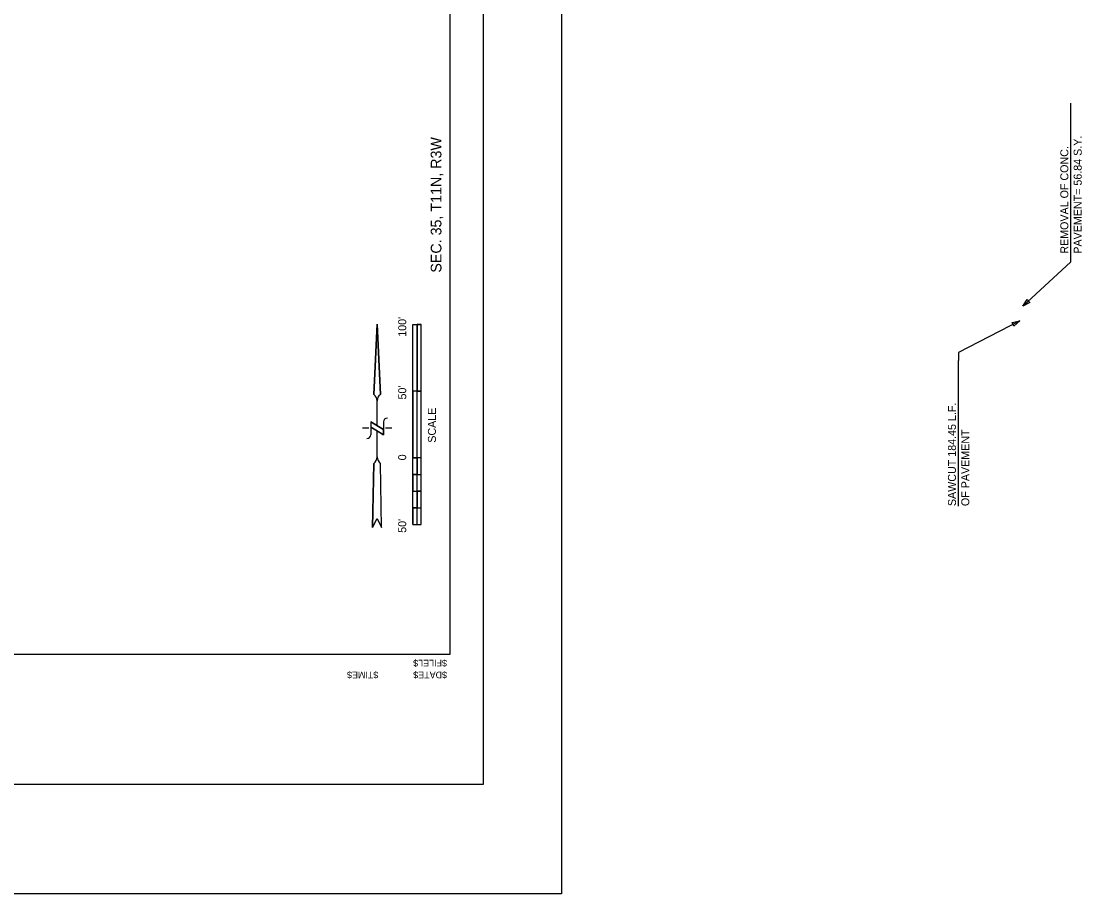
# Model space of a CAD drawing. Extents: x 2150645 to 2152288, y 141590 to 143592.
# Drawn here: x 2151440 to 2152235, y 141792 to 142447 of the extents above; entities that cross this region are included whole.
import ezdxf

# ---------------------------------------------------------------- set-up
doc = ezdxf.new("R2010")
doc.units = 0
for name, color, linetype in [('1', 7, 'Continuous'), ('EX_Align', 7, 'Continuous'), ('INR_InRoads_Unassigned', 7, 'Continuous'), ('INR_Tracking', 7, 'Continuous'), ('PR_Align_Ramp_D', 7, 'Continuous'), ('SHT_Plot_Stamp', 7, 'Continuous'), ('TOPO_DRAIN_Headwall', 7, 'Continuous'), ('TOPO_San Manhole', 7, 'Continuous')]:
    doc.layers.add(name, color=color, linetype=linetype)

msp = doc.modelspace()

# ---------------------------------------------------------------- linework, layer by layer
at = {"layer": '1'}
for p, q in [((2151704.66, 142166.54), (2151707.07, 142219.43)), ((2151707.07, 142219.43), (2151704.66, 142166.54)), ((2151707.07, 142219.43), (2151709.47, 142166.54)), ((2151709.47, 142166.54), (2151707.07, 142219.43)), ((2151707.07, 142143.15), (2151707.07, 142161.86)), ((2151700.83, 142141.23), (2151696.03, 142141.23)), ((2151711.87, 142140.28), (2151702.27, 142146.03)), ((2151702.27, 142146.03), (2151711.87, 142140.28)), ((2151702.27, 142146.03), (2151702.27, 142136.44)), ((2151707.07, 142143.15), (2151702.27, 142146.03)), ((2151702.27, 142146.03), (2151702.27, 142142.19)), ((2151711.87, 142136.44), (2151702.27, 142142.19)), ((2151711.87, 142140.28), (2151707.07, 142143.15)), ((2151707.07, 142119.65), (2151707.07, 142139.32)), ((2151711.87, 142146.03), (2151711.87, 142136.44)), ((2151711.87, 142136.44), (2151711.87, 142140.28)), ((2151718.1, 142141.23), (2151713.31, 142141.23)), ((2151703.71, 142066.87), (2151704.67, 142114.85)), ((2151704.67, 142114.85), (2151703.71, 142066.87)), ((2151710.43, 142066.87), (2151709.47, 142114.85)), ((2151710.43, 142066.87), (2151709.47, 142114.85)), ((2151703.71, 142066.87), (2151707.07, 142073.59)), ((2151703.71, 142066.87), (2151707.07, 142073.59)), ((2151707.07, 142073.59), (2151710.43, 142066.87)), ((2151707.07, 142073.59), (2151710.43, 142066.87))]:
    msp.add_line(p, q, dxfattribs=at)
for points in [[(2151702.27, 142142.19), (2151707.07, 142139.32), (2151711.87, 142136.44)], [(2151707.08, 142119.65), (2151707.07, 142119.65), (2151707.06, 142119.65)]]:
    msp.add_lwpolyline(points, dxfattribs=at)
for centre, radius, start, end in [((2151701.31, 142161.86), 5.76, 360, 54.38016), ((2151701.31, 142161.86), 5.76, 360, 54.38016), ((2151712.83, 142161.86), 5.76, 125.61984, 180), ((2151712.83, 142161.86), 5.76, 125.61984, 180), ((2151714.74, 142146.03), 2.88, 90, 180), ((2151699.39, 142136.44), 2.88, 270, 360), ((2151698.72, 142120.81), 8.43, 314.95671, 352.41889), ((2151698.72, 142120.81), 8.43, 314.95671, 352.059), ((2151715.42, 142120.81), 8.43, 187.58111, 225.04329), ((2151715.42, 142120.81), 8.43, 187.941, 225.04329)]:
    msp.add_arc(centre, radius, start, end, dxfattribs=at)
at = {"layer": 'EX_Align'}
msp.add_lwpolyline([(2150645.33, 141792.07), (2150645.33, 143592.07), (2151845.33, 143592.07), (2151845.33, 141792.07)], close=True, dxfattribs=at)
at = {"layer": 'INR_Tracking'}
for p, q in [((2151733.89, 142219.16), (2151737.01, 142219.16)), ((2151733.89, 142069.16), (2151733.89, 142219.16)), ((2151737.01, 142219.16), (2151740.14, 142219.16)), ((2151737.01, 142119.16), (2151737.01, 142219.16)), ((2151740.14, 142219.16), (2151737.01, 142219.16)), ((2151737.01, 142219.16), (2151737.01, 142169.16)), ((2151740.14, 142069.16), (2151740.14, 142219.16)), ((2151740.14, 142169.16), (2151740.14, 142219.16)), ((2151737.01, 142169.16), (2151733.89, 142169.16)), ((2151737.01, 142169.16), (2151733.89, 142169.16)), ((2151733.89, 142169.16), (2151733.89, 142119.16)), ((2151740.14, 142169.16), (2151737.01, 142169.16)), ((2151737.01, 142119.16), (2151737.01, 142169.16)), ((2151737.01, 142169.16), (2151740.14, 142169.16)), ((2151737.01, 142119.16), (2151733.89, 142119.16)), ((2151733.89, 142119.16), (2151737.01, 142119.16)), ((2151740.14, 142119.16), (2151737.01, 142119.16)), ((2151737.01, 142106.66), (2151737.01, 142119.16)), ((2151740.14, 142119.16), (2151737.01, 142119.16)), ((2151737.01, 142119.16), (2151737.01, 142106.66)), ((2151740.14, 142106.66), (2151740.14, 142119.16)), ((2151733.89, 142106.66), (2151740.14, 142106.66)), ((2151737.01, 142106.66), (2151733.89, 142106.66)), ((2151733.89, 142106.66), (2151733.89, 142094.16)), ((2151737.01, 142094.16), (2151737.01, 142106.66)), ((2151737.01, 142094.16), (2151737.01, 142106.66)), ((2151737.01, 142106.66), (2151740.14, 142106.66)), ((2151733.89, 142094.16), (2151740.14, 142094.16)), ((2151733.89, 142094.16), (2151740.14, 142094.16)), ((2151733.89, 142094.16), (2151737.01, 142094.16)), ((2151737.01, 142081.66), (2151737.01, 142094.16)), ((2151740.14, 142094.16), (2151737.01, 142094.16)), ((2151737.01, 142094.16), (2151737.01, 142081.66)), ((2151740.14, 142081.66), (2151740.14, 142094.16)), ((2151733.89, 142081.66), (2151740.14, 142081.66)), ((2151737.01, 142081.66), (2151733.89, 142081.66)), ((2151733.89, 142081.66), (2151733.89, 142069.16)), ((2151737.01, 142069.16), (2151737.01, 142081.66)), ((2151737.01, 142069.16), (2151737.01, 142081.66)), ((2151737.01, 142081.66), (2151740.14, 142081.66)), ((2151733.89, 142069.16), (2151740.14, 142069.16)), ((2151733.89, 142069.16), (2151737.01, 142069.16))]:
    msp.add_line(p, q, dxfattribs=at)
at = {"layer": 'PR_Align_Ramp_D'}
msp.add_lwpolyline([(2151761.58, 143546.45), (2151761.58, 141971.45), (2150711.58, 141971.45), (2150711.58, 143546.45)], close=True, dxfattribs=at)
at = {"layer": 'TOPO_DRAIN_Headwall'}
msp.add_lwpolyline([(2150686.58, 141873.95), (2150686.58, 143573.95), (2151786.58, 143573.95), (2151786.58, 141873.95)], close=True, dxfattribs=at)
at = {"layer": 'TOPO_San Manhole'}
for p, q in [((2152227.16, 142272.18), (2152227.16, 142385.16)), ((2152142.93, 142082.88), (2152142.93, 142191.96))]:
    msp.add_line(p, q, dxfattribs=at)
for points in [[(2152191, 142232.8), (2152227.16, 142266.18), (2152227.16, 142272.18)], [(2152188.88, 142221.92), (2152142.93, 142197.96), (2152142.93, 142191.96)]]:
    msp.add_lwpolyline(points, dxfattribs=at)
for points in [[(2152191, 142232.8), (2152194.29, 142237.82), (2152196.26, 142235.68)], [(2152188.88, 142221.92), (2152184.39, 142217.94), (2152183.05, 142220.52)]]:
    msp.add_lwpolyline(points, close=True, dxfattribs=at)

# ---------------------------------------------------------------- texts
at = {"layer": 'INR_InRoads_Unassigned'}
msp.add_text('SEC. 35, T11N, R3W', height=8, rotation=90.02698, dxfattribs=at).set_placement((2151755.29, 142257.96))
at = {"layer": 'INR_Tracking'}
for s, p in [("100'", (2151728.89, 142209.86)), ("50'", (2151728.89, 142162.81)), ('SCALE', (2151751.14, 142130.4)), ('0', (2151728.89, 142117.19)), ("50'", (2151728.89, 142062.81))]:
    msp.add_text(s, height=6, rotation=90, dxfattribs=at).set_placement(p)
at = {"layer": 'SHT_Plot_Stamp'}
for s, p in [('$FILEL$', (2151759.45, 141967.58)), ('$TIME$', (2151707.96, 141958.71)), ('$DATE$', (2151759.45, 141958.71))]:
    msp.add_text(s, height=5, rotation=180, dxfattribs=at).set_placement(p)
at = {"layer": 'TOPO_San Manhole'}
for s, p in [('PAVEMENT= 56.84 S.Y.', (2152235.16, 142272.18)), ('REMOVAL OF CONC.', (2152225.16, 142272.18)), ('SAWCUT 184.45 L.F. ', (2152140.93, 142082.88)), ('OF PAVEMENT', (2152150.93, 142082.88))]:
    msp.add_text(s, height=6, rotation=90, dxfattribs=at).set_placement(p)

doc.saveas('drawing.dxf')
